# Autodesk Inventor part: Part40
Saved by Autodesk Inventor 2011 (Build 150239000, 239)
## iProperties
Created: 2010-10
Part Number: Part40
Document SubType Name: Modeling
Designer: tribel
Density: 1 g/cm^3
Author: tribel
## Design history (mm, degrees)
feature "Base1"
body "Solid1"
